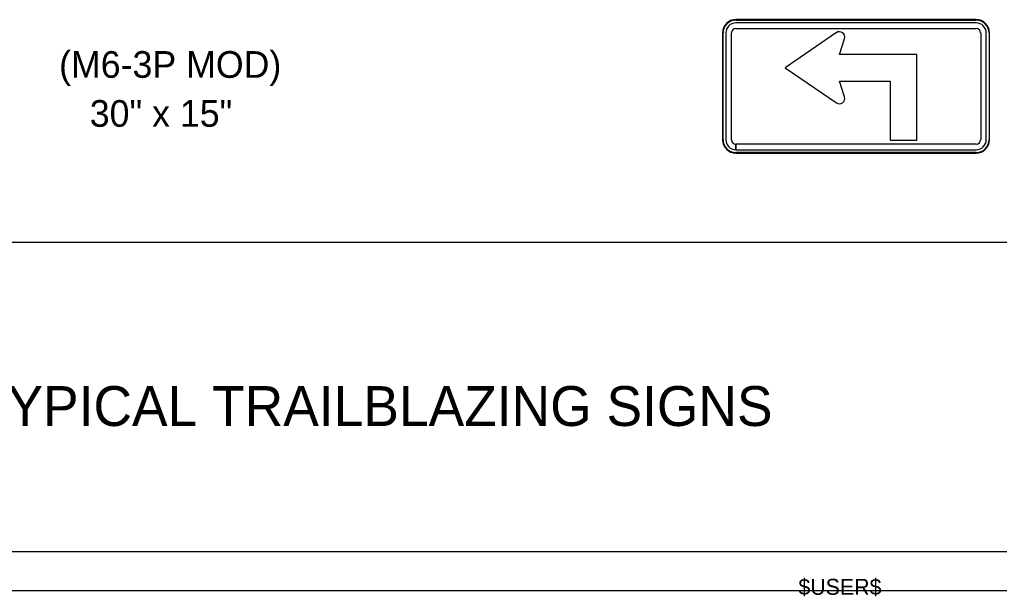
# Model space of a CAD drawing. Extents: x 17890587 to 17890754, y 17897693 to 17897992.
# Drawn here: x 17890622.18 to 17890629.61, y 17897873.06 to 17897877.43 of the extents above; entities that cross this region are included whole.
import ezdxf

# ---------------------------------------------------------------- set-up
doc = ezdxf.new("R2010")
doc.units = 0
for name, color, linetype in [('GSBWFill', 7, 'Continuous'), ('GSColorFill', 7, 'Continuous'), ('GSOutline', 7, 'Continuous'), ('PlotBorder_dp', 7, 'Continuous'), ('SheetBorder_dp', 7, 'Continuous'), ('TextMisc', 7, 'Continuous')]:
    doc.layers.add(name, color=color, linetype=linetype)

msp = doc.modelspace()

# ---------------------------------------------------------------- linework, layer by layer
at = {"layer": 'GSBWFill'}
msp.add_line((17890628.4322, 17897876.8471), (17890628.3943, 17897876.9665), dxfattribs=at)
for points in [[(17890628.3707, 17897877.334), (17890627.9826, 17897877.0677), (17890628.3707, 17897876.8016)], [(17890628.3943, 17897876.9665), (17890628.7781, 17897876.9665), (17890628.7781, 17897876.5183), (17890628.9805, 17897876.5183), (17890628.9805, 17897877.169), (17890628.3943, 17897877.169), (17890628.4322, 17897877.2883)]]:
    msp.add_lwpolyline(points, dxfattribs=at)
for centre, major_axis, start_param, end_param in [((17890628.3936, 17897877.3006), (0.0405, 0), 5.975991, 8.455234), ((17890628.3936, 17897876.8349), (-0.0405, 0), 0.969544, 3.448787)]:
    msp.add_ellipse(centre, major_axis=major_axis, ratio=0.999895, start_param=start_param, end_param=end_param, dxfattribs=at)
at = {"layer": 'GSColorFill'}
for p, q in [((17890629.4302, 17897877.4331), (17890627.6079, 17897877.4331)), ((17890629.4302, 17897877.4331), (17890627.6079, 17897877.4331)), ((17890627.6079, 17897877.4289), (17890629.4302, 17897877.4289)), ((17890629.4302, 17897877.4078), (17890627.6079, 17897877.4078)), ((17890627.5066, 17897877.3318), (17890627.5066, 17897876.5219)), ((17890627.5066, 17897877.3318), (17890627.5066, 17897876.5219)), ((17890627.5109, 17897876.5219), (17890627.5109, 17897877.3318)), ((17890627.532, 17897877.3318), (17890627.532, 17897876.5219)), ((17890627.5741, 17897876.5219), (17890627.5741, 17897877.3318)), ((17890627.6079, 17897877.3656), (17890629.4302, 17897877.3656)), ((17890629.464, 17897877.3318), (17890629.464, 17897876.5219)), ((17890629.5061, 17897876.5219), (17890629.5061, 17897877.3318)), ((17890629.5272, 17897877.3318), (17890629.5272, 17897876.5219)), ((17890629.5314, 17897876.5219), (17890629.5314, 17897877.3318)), ((17890629.5314, 17897876.5219), (17890629.5314, 17897877.3318)), ((17890628.4322, 17897876.8471), (17890628.3943, 17897876.9665)), ((17890627.6079, 17897876.446), (17890627.6079, 17897876.4882)), ((17890629.4302, 17897876.4882), (17890627.6083, 17897876.4882)), ((17890627.6083, 17897876.4882), (17890627.6083, 17897876.446)), ((17890627.6079, 17897876.4207), (17890627.6079, 17897876.4249)), ((17890629.4302, 17897876.4249), (17890627.6079, 17897876.4249)), ((17890627.6079, 17897876.4249), (17890627.6079, 17897876.4207)), ((17890627.6079, 17897876.4207), (17890629.4302, 17897876.4207)), ((17890627.6079, 17897876.4207), (17890629.4302, 17897876.4207)), ((17890627.6083, 17897876.446), (17890629.4302, 17897876.446))]:
    msp.add_line(p, q, dxfattribs=at)
for points in [[(17890628.3707, 17897877.334), (17890627.9826, 17897877.0677), (17890628.3707, 17897876.8016)], [(17890628.3943, 17897876.9665), (17890628.7781, 17897876.9665), (17890628.7781, 17897876.5183), (17890628.9805, 17897876.5183), (17890628.9805, 17897877.169), (17890628.3943, 17897877.169), (17890628.4322, 17897877.2883)]]:
    msp.add_lwpolyline(points, dxfattribs=at)
for centre, radius, start, end in [((17890627.6079, 17897877.3318), 0.1012, 90, 180), ((17890627.6079, 17897877.3318), 0.1012, 90, 180), ((17890627.6079, 17897877.3318), 0.097, 90, 180), ((17890627.6079, 17897877.3318), 0.0759, 90, 180), ((17890629.4302, 17897877.3318), 0.1012, 0, 90), ((17890629.4302, 17897877.3318), 0.1012, 0, 90), ((17890629.4302, 17897877.3318), 0.097, 0, 90), ((17890629.4302, 17897877.3318), 0.0759, 0, 90), ((17890627.6079, 17897877.3318), 0.0337, 90, 180), ((17890629.4302, 17897877.3318), 0.0337, 0, 90), ((17890627.6079, 17897876.5219), 0.1012, 180, 270), ((17890627.6079, 17897876.5219), 0.1012, 180, 270), ((17890627.6079, 17897876.5219), 0.097, 180, 270), ((17890627.6079, 17897876.5219), 0.0759, 180, 270), ((17890627.6079, 17897876.5219), 0.0337, 180, 270), ((17890629.4302, 17897876.5219), 0.1012, 270, 0), ((17890629.4302, 17897876.5219), 0.1012, 270, 0), ((17890629.4302, 17897876.5219), 0.097, 270, 0), ((17890629.4302, 17897876.5219), 0.0759, 270, 0), ((17890629.4302, 17897876.5219), 0.0337, 270, 0)]:
    msp.add_arc(centre, radius, start, end, dxfattribs=at)
for centre, major_axis, start_param, end_param in [((17890628.3936, 17897877.3006), (0.0405, 0), 5.975991, 8.455234), ((17890628.3936, 17897876.8349), (-0.0405, 0), 0.969544, 3.448787)]:
    msp.add_ellipse(centre, major_axis=major_axis, ratio=0.999895, start_param=start_param, end_param=end_param, dxfattribs=at)
at = {"layer": 'GSOutline'}
msp.add_line((17890628.4322, 17897876.8471), (17890628.3943, 17897876.9665), dxfattribs=at)
for points in [[(17890628.3707, 17897877.334), (17890627.9826, 17897877.0677), (17890628.3707, 17897876.8016)], [(17890628.3943, 17897876.9665), (17890628.7781, 17897876.9665), (17890628.7781, 17897876.5183), (17890628.9805, 17897876.5183), (17890628.9805, 17897877.169), (17890628.3943, 17897877.169), (17890628.4322, 17897877.2883)]]:
    msp.add_lwpolyline(points, dxfattribs=at)
for centre, major_axis, start_param, end_param in [((17890628.3936, 17897877.3006), (0.0405, 0), 5.975991, 8.455234), ((17890628.3936, 17897876.8349), (-0.0405, 0), 0.969544, 3.448787)]:
    msp.add_ellipse(centre, major_axis=major_axis, ratio=0.999895, start_param=start_param, end_param=end_param, dxfattribs=at)
at = {"layer": 'PlotBorder_dp'}
msp.add_lwpolyline([(17890586.7562, 17897873.1039), (17890635.165, 17897873.1039), (17890635.165, 17897904.2029), (17890586.7562, 17897904.2029)], close=True, dxfattribs=at)
at = {"layer": 'SheetBorder_dp'}
for p, q in [((17890588.3699, 17897875.7444), (17890633.5514, 17897875.7444)), ((17890588.3699, 17897873.3973), (17890633.5514, 17897873.3973))]:
    msp.add_line(p, q, dxfattribs=at)

# ---------------------------------------------------------------- texts
at = {"layer": 'TextMisc'}
for s, height, p in [('(M6-3P MOD)', 0.202479, (17890622.4774, 17897876.9915)), ('30" x 15"', 0.20248, (17890622.7099, 17897876.62)), ('TYPICAL TRAILBLAZING SIGNS', 0.302553, (17890621.8386, 17897874.3505)), ('$USER$', 0.12102, (17890628.0822, 17897873.0701))]:
    msp.add_text(s, height=height, dxfattribs=at).set_placement(p)

doc.saveas('drawing.dxf')
